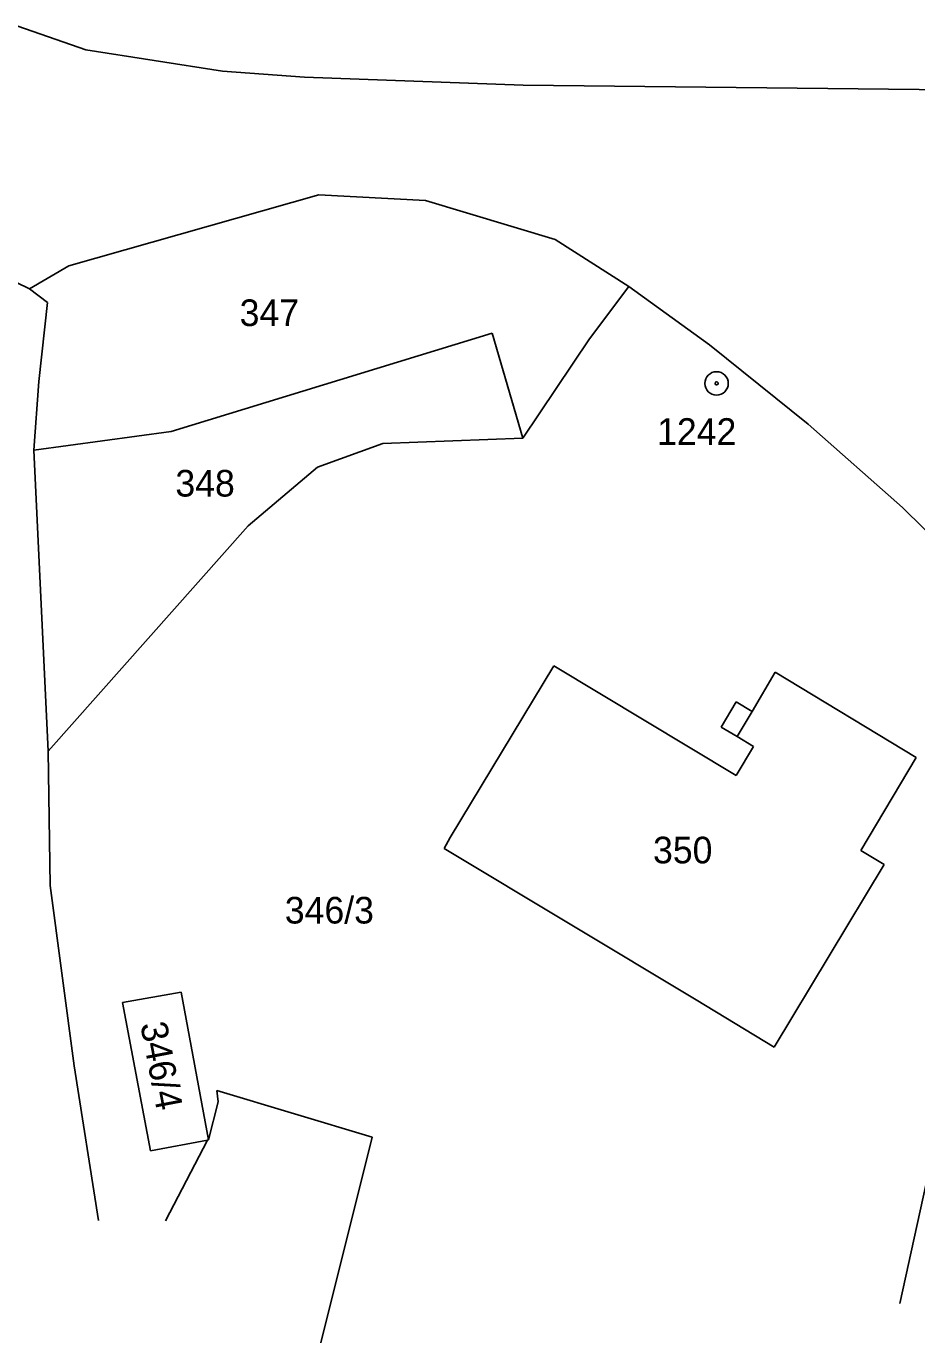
# Model space of a CAD drawing. Extents: x -621172 to -616925, y -1123899 to -1119548.
# Drawn here: x -619154.3 to -619097.5, y -1121645.9 to -1121561.8 of the extents above; entities that cross this region are included whole.
import ezdxf

# ---------------------------------------------------------------- set-up
doc = ezdxf.new("R2010")
doc.units = 0
for name, color, linetype in [('Vrstva 1', 7, 'Continuous'), ('Vrstva 17', 7, 'Continuous'), ('Vrstva 18', 7, 'Continuous'), ('Vrstva 19', 7, 'Continuous'), ('Vrstva 24', 7, 'Continuous'), ('Vrstva 4', 7, 'Continuous')]:
    doc.layers.add(name, color=color, linetype=linetype)

msp = doc.modelspace()

# ---------------------------------------------------------------- linework, layer by layer
at = {"layer": 'Vrstva 1'}
for points in [[(-619154.85, -1121561.84), (-619150.51, -1121563.35)], [(-619141.79, -1121564.7), (-619150.51, -1121563.35)], [(-619136.56, -1121565.09), (-619141.79, -1121564.7)], [(-619122.59, -1121565.6), (-619136.56, -1121565.09)], [(-619089.55, -1121565.96), (-619122.59, -1121565.6)], [(-619135.65, -1121572.6), (-619151.61, -1121577.12)], [(-619128.84, -1121572.95), (-619135.65, -1121572.6)], [(-619120.56, -1121575.44), (-619128.84, -1121572.95)], [(-619154.11, -1121578.6), (-619162.88, -1121574.33)], [(-619115.86, -1121578.44), (-619120.56, -1121575.44)], [(-619151.61, -1121577.12), (-619154.11, -1121578.6)], [(-619152.96, -1121579.46), (-619154.11, -1121578.6)], [(-619118.36, -1121581.78), (-619115.86, -1121578.44)], [(-619115.86, -1121578.44), (-619110.7, -1121582.17)], [(-619153.51, -1121584.51), (-619152.96, -1121579.46)], [(-619145.06, -1121587.7), (-619124.57, -1121581.42)], [(-619124.57, -1121581.42), (-619122.62, -1121588.13)], [(-619122.62, -1121588.13), (-619118.36, -1121581.78)], [(-619110.7, -1121582.17), (-619104.4, -1121587.23)], [(-619153.84, -1121588.89), (-619153.51, -1121584.51)], [(-619104.4, -1121587.23), (-619098.37, -1121592.54)], [(-619153.84, -1121588.89), (-619145.06, -1121587.7)], [(-619152.92, -1121608.11), (-619153.84, -1121588.89)], [(-619135.73, -1121589.97), (-619131.56, -1121588.46)], [(-619122.62, -1121588.13), (-619131.56, -1121588.46)], [(-619140.16, -1121593.71), (-619135.73, -1121589.97)], [(-619090.17, -1121600.63), (-619098.37, -1121592.54)], [(-619152.92, -1121608.11), (-619140.16, -1121593.71)], [(-619120.64, -1121602.65), (-619127.25, -1121613.62)], [(-619109, -1121609.65), (-619120.64, -1121602.65)], [(-619106.5, -1121603.05), (-619107.98, -1121605.57)], [(-619097.5, -1121608.5), (-619106.5, -1121603.05)], [(-619109, -1121604.96), (-619109.96, -1121606.56)], [(-619107.98, -1121605.57), (-619109, -1121604.96)], [(-619109.96, -1121606.56), (-619108.94, -1121607.17)], [(-619108.94, -1121607.17), (-619107.9, -1121607.8)], [(-619152.8, -1121616.68), (-619152.92, -1121608.11)], [(-619107.9, -1121607.8), (-619109, -1121609.65)], [(-619101.04, -1121614.44), (-619097.5, -1121608.5)], [(-619127.25, -1121613.62), (-619127.65, -1121614.31)], [(-619127.65, -1121614.31), (-619111.56, -1121623.97)], [(-619099.55, -1121615.33), (-619101.04, -1121614.44)], [(-619106.57, -1121627), (-619099.55, -1121615.33)], [(-619151.26, -1121628.19), (-619152.8, -1121616.68)], [(-619148.18, -1121624.15), (-619144.42, -1121623.47)], [(-619146.39, -1121633.61), (-619148.18, -1121624.15)], [(-619142.69, -1121632.91), (-619144.42, -1121623.47)], [(-619111.56, -1121623.97), (-619106.57, -1121627)], [(-619095.04, -1121627.35), (-619098.54, -1121643.34)], [(-619149.71, -1121638.05), (-619151.26, -1121628.19)], [(-619142.15, -1121629.75), (-619142.06, -1121630.47)], [(-619142.15, -1121629.75), (-619132.24, -1121632.73)], [(-619142.06, -1121630.47), (-619142.69, -1121632.91)], [(-619146.39, -1121633.61), (-619142.74, -1121632.92)], [(-619145.44, -1121638.08), (-619142.74, -1121632.92)], [(-619142.74, -1121632.92), (-619142.69, -1121632.91)], [(-619132.24, -1121632.73), (-619135.52, -1121645.85)]]:
    msp.add_lwpolyline(points, dxfattribs=at)
at = {"layer": 'Vrstva 24'}
for radius in [0.75, 0.1]:
    msp.add_circle((-619110.25, -1121584.63), radius, dxfattribs=at)
at = {"layer": 'Vrstva 4'}
msp.add_lwpolyline([(-619107.98, -1121605.57), (-619108.94, -1121607.17)], dxfattribs=at)

# ---------------------------------------------------------------- texts
at = {"layer": 'Vrstva 17'}
msp.add_text('1242', height=1.7, dxfattribs=at).set_placement((-619114.046, -1121588.55))
at = {"layer": 'Vrstva 18'}
for s, p in [('347', (-619140.696, -1121580.97)), ('348', (-619144.799, -1121591.85)), ('346/3', (-619137.813, -1121619.1))]:
    msp.add_text(s, height=1.7, dxfattribs=at).set_placement(p)
at = {"layer": 'Vrstva 19'}
msp.add_text('350', height=1.7, dxfattribs=at).set_placement((-619114.306, -1121615.26))
msp.add_text('346/4', height=1.7, rotation=280.8, dxfattribs=at).set_placement((-619147.047, -1121625.528))

doc.saveas('drawing.dxf')
